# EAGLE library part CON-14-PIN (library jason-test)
14-pin connector
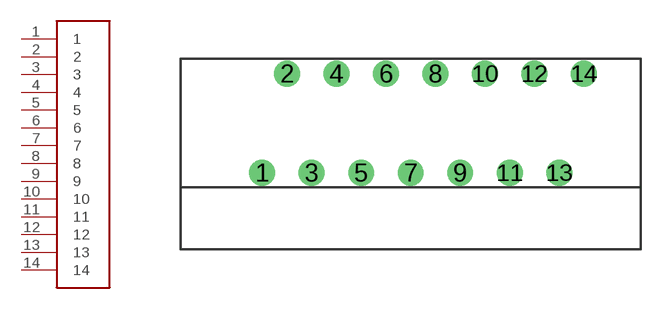
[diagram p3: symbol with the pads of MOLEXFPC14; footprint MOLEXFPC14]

Designator prefix -

## CON-14-PIN  [MOLEXFPC14]
1  1
2  2
3  3
4  4
5  5
6  6
7  7
8  8
9  9
10  10
11  11
12  12
13  13
14  14

## Footprint MOLEXFPC14 (pad centres in mm)
Molex FFC/FPC 14-pin connector (R/A, ZIF)
drill 0.8 round: 1 -7.5,-2.5; 2 -6.25,2.5; 3 -5,-2.5; 4 -3.75,2.5; 5 -2.5,-2.5; 6 -1.25,2.5; 7 0,-2.5; 8 1.25,2.5; 9 2.5,-2.5; 10 3.75,2.5; 11 5,-2.5; 12 6.25,2.5; 13 7.5,-2.5; 14 8.75,2.5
